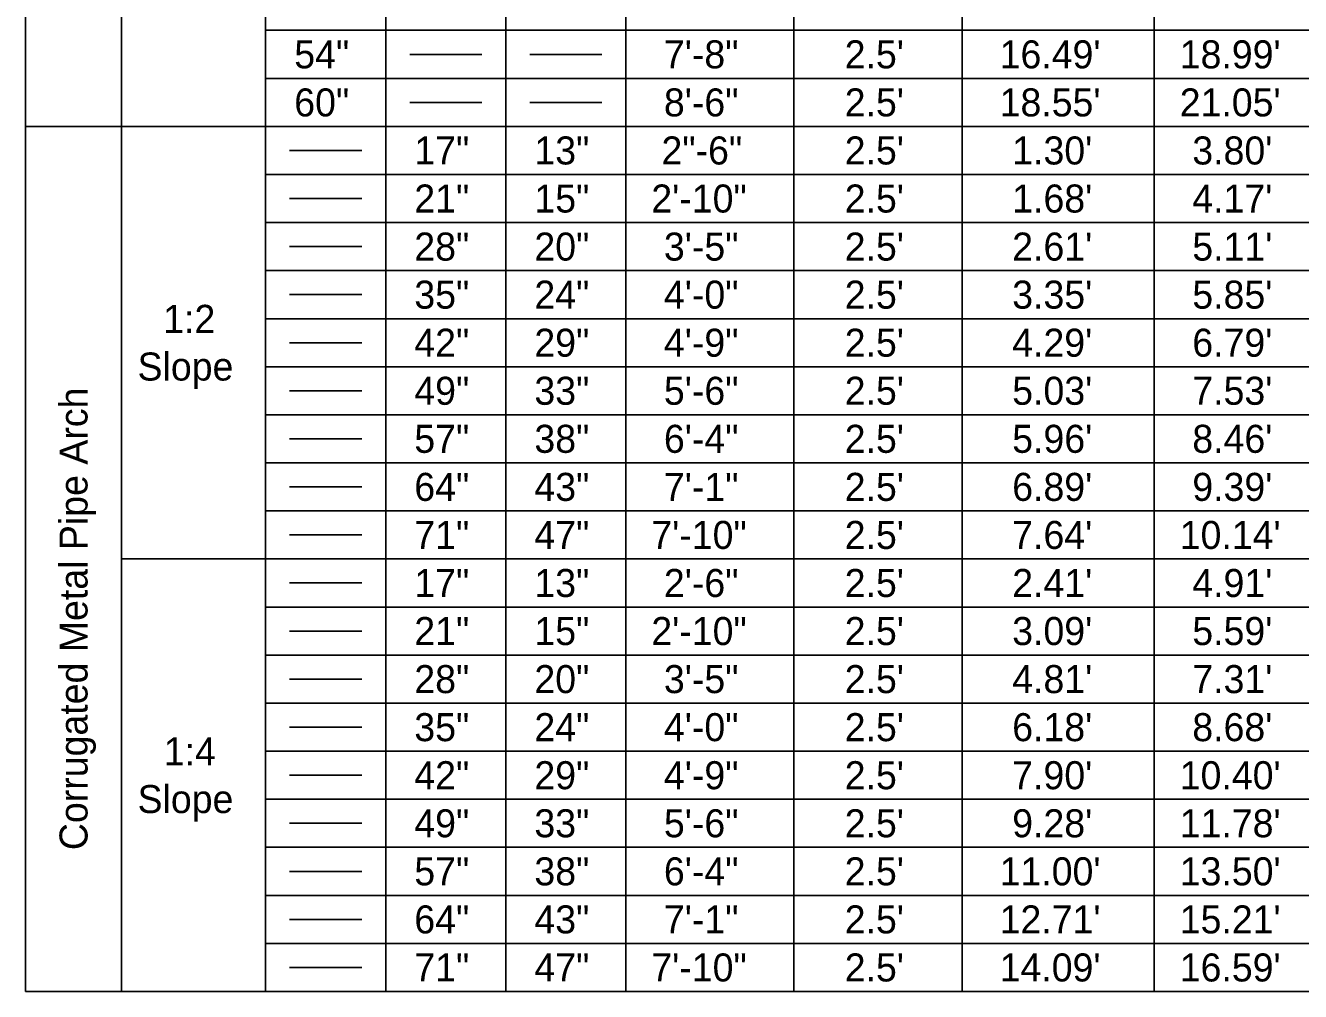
# Model space of a CAD drawing. Extents: x 1.7 to 14.4, y 0 to 7.8.
# Drawn here: x 1.7 to 4.886, y 2.49 to 4.902 of the extents above; entities that cross this region are included whole.
import ezdxf

# ---------------------------------------------------------------- set-up
doc = ezdxf.new("R2010")
doc.units = 0
doc.layers.add('Table', color=7, linetype='Continuous')

msp = doc.modelspace()

# ---------------------------------------------------------------- linework, layer by layer
at = {"layer": 'Table'}
for p, q in [((2.66, 4.83), (2.84, 4.83)), ((2.96, 4.83), (3.14, 4.83)), ((2.66, 4.71), (2.84, 4.71)), ((2.96, 4.71), (3.14, 4.71)), ((2.36, 4.59), (2.54, 4.59)), ((2.36, 4.47), (2.54, 4.47)), ((2.36, 4.35), (2.54, 4.35)), ((2.36, 4.23), (2.54, 4.23)), ((2.36, 4.11), (2.54, 4.11)), ((2.36, 3.99), (2.54, 3.99)), ((2.36, 3.87), (2.54, 3.87)), ((2.36, 3.75), (2.54, 3.75)), ((2.36, 3.63), (2.54, 3.63)), ((2.36, 3.51), (2.54, 3.51)), ((2.36, 3.39), (2.54, 3.39)), ((2.36, 3.27), (2.54, 3.27)), ((2.36, 3.15), (2.54, 3.15)), ((2.36, 3.03), (2.54, 3.03)), ((2.36, 2.91), (2.54, 2.91)), ((2.36, 2.79), (2.54, 2.79)), ((2.36, 2.67), (2.54, 2.67)), ((2.36, 2.55), (2.54, 2.55))]:
    msp.add_line(p, q, dxfattribs=at)
for points in [[(1.94, 7.7524), (1.94, 7.17), (1.94, 6.81), (1.94, 5.73), (1.94, 4.65), (1.94, 3.57), (1.94, 2.49)], [(1.7, 6.81), (1.7, 4.65), (1.7, 2.49)], [(2.3, 5.01), (2.3, 4.89), (2.3, 4.77), (2.3, 4.65), (2.3, 4.53), (2.3, 4.41), (2.3, 4.29), (2.3, 4.17), (2.3, 4.05), (2.3, 3.93), (2.3, 3.81), (2.3, 3.69), (2.3, 3.57), (2.3, 3.45), (2.3, 3.33), (2.3, 3.21), (2.3, 3.09), (2.3, 2.97), (2.3, 2.85), (2.3, 2.73), (2.3, 2.61), (2.3, 2.49)], [(2.6, 5.01), (2.6, 4.89), (2.6, 4.77), (2.6, 4.65), (2.6, 4.53), (2.6, 4.41), (2.6, 4.29), (2.6, 4.17), (2.6, 4.05), (2.6, 3.93), (2.6, 3.81), (2.6, 3.69), (2.6, 3.57), (2.6, 3.45), (2.6, 3.33), (2.6, 3.21), (2.6, 3.09), (2.6, 2.97), (2.6, 2.85), (2.6, 2.73), (2.6, 2.61), (2.6, 2.49)], [(2.9, 5.01), (2.9, 4.89), (2.9, 4.77), (2.9, 4.65), (2.9, 4.53), (2.9, 4.41), (2.9, 4.29), (2.9, 4.17), (2.9, 4.05), (2.9, 3.93), (2.9, 3.81), (2.9, 3.69), (2.9, 3.57), (2.9, 3.45), (2.9, 3.33), (2.9, 3.21), (2.9, 3.09), (2.9, 2.97), (2.9, 2.85), (2.9, 2.73), (2.9, 2.61), (2.9, 2.49)], [(3.2, 5.01), (3.2, 4.89), (3.2, 4.77), (3.2, 4.65), (3.2, 4.53), (3.2, 4.41), (3.2, 4.29), (3.2, 4.17), (3.2, 4.05), (3.2, 3.93), (3.2, 3.81), (3.2, 3.69), (3.2, 3.57), (3.2, 3.45), (3.2, 3.33), (3.2, 3.21), (3.2, 3.09), (3.2, 2.97), (3.2, 2.85), (3.2, 2.73), (3.2, 2.61), (3.2, 2.49)], [(3.62, 5.01), (3.62, 4.89), (3.62, 4.77), (3.62, 4.65), (3.62, 4.53), (3.62, 4.41), (3.62, 4.29), (3.62, 4.17), (3.62, 4.05), (3.62, 3.93), (3.62, 3.81), (3.62, 3.69), (3.62, 3.57), (3.62, 3.45), (3.62, 3.33), (3.62, 3.21), (3.62, 3.09), (3.62, 2.97), (3.62, 2.85), (3.62, 2.73), (3.62, 2.61), (3.62, 2.49)], [(4.04, 5.01), (4.04, 4.89), (4.04, 4.77), (4.04, 4.65), (4.04, 4.53), (4.04, 4.41), (4.04, 4.29), (4.04, 4.17), (4.04, 4.05), (4.04, 3.93), (4.04, 3.81), (4.04, 3.69), (4.04, 3.57), (4.04, 3.45), (4.04, 3.33), (4.04, 3.21), (4.04, 3.09), (4.04, 2.97), (4.04, 2.85), (4.04, 2.73), (4.04, 2.61), (4.04, 2.49)], [(4.52, 5.01), (4.52, 4.89), (4.52, 4.77), (4.52, 4.65), (4.52, 4.53), (4.52, 4.41), (4.52, 4.29), (4.52, 4.17), (4.52, 4.05), (4.52, 3.93), (4.52, 3.81), (4.52, 3.69), (4.52, 3.57), (4.52, 3.45), (4.52, 3.33), (4.52, 3.21), (4.52, 3.09), (4.52, 2.97), (4.52, 2.85), (4.52, 2.73), (4.52, 2.61), (4.52, 2.49)], [(2.3, 4.89), (2.6, 4.89), (2.9, 4.89), (3.2, 4.89), (3.62, 4.89), (4.04, 4.89), (4.52, 4.89), (4.94, 4.89), (5.3, 4.89), (5.66, 4.89), (6.02, 4.89), (6.38, 4.89), (6.8, 4.89), (7.22, 4.89), (7.64, 4.89), (8.06, 4.89), (8.42, 4.89)], [(2.3, 4.77), (2.6, 4.77), (2.9, 4.77), (3.2, 4.77), (3.62, 4.77), (4.04, 4.77), (4.52, 4.77), (4.94, 4.77), (5.3, 4.77), (5.66, 4.77), (6.02, 4.77), (6.38, 4.77), (6.8, 4.77), (7.22, 4.77), (7.64, 4.77), (8.06, 4.77), (8.42, 4.77)], [(1.7, 4.65), (1.94, 4.65), (2.3, 4.65), (2.6, 4.65), (2.9, 4.65), (3.2, 4.65), (3.62, 4.65), (4.04, 4.65), (4.52, 4.65), (4.94, 4.65), (5.3, 4.65), (5.66, 4.65), (6.02, 4.65), (6.38, 4.65), (6.8, 4.65), (7.22, 4.65), (7.64, 4.65), (8.06, 4.65), (8.42, 4.65)], [(2.3, 4.53), (2.6, 4.53), (2.9, 4.53), (3.2, 4.53), (3.62, 4.53), (4.04, 4.53), (4.52, 4.53), (4.94, 4.53), (5.3, 4.53), (5.66, 4.53), (6.02, 4.53), (6.38, 4.53), (6.8, 4.53), (7.22, 4.53), (7.64, 4.53), (8.06, 4.53), (8.42, 4.53)], [(2.3, 4.41), (2.6, 4.41), (2.9, 4.41), (3.2, 4.41), (3.62, 4.41), (4.04, 4.41), (4.52, 4.41), (4.94, 4.41), (5.3, 4.41), (5.66, 4.41), (6.02, 4.41), (6.38, 4.41), (6.8, 4.41), (7.22, 4.41), (7.64, 4.41), (8.06, 4.41), (8.42, 4.41)], [(2.3, 4.29), (2.6, 4.29), (2.9, 4.29), (3.2, 4.29), (3.62, 4.29), (4.04, 4.29), (4.52, 4.29), (4.94, 4.29), (5.3, 4.29), (5.66, 4.29), (6.02, 4.29), (6.38, 4.29), (6.8, 4.29), (7.22, 4.29), (7.64, 4.29), (8.06, 4.29), (8.42, 4.29)], [(2.3, 4.17), (2.6, 4.17), (2.9, 4.17), (3.2, 4.17), (3.62, 4.17), (4.04, 4.17), (4.52, 4.17), (4.94, 4.17), (5.3, 4.17), (5.66, 4.17), (6.02, 4.17), (6.38, 4.17), (6.8, 4.17), (7.22, 4.17), (7.64, 4.17), (8.06, 4.17), (8.42, 4.17)], [(2.3, 4.05), (2.6, 4.05), (2.9, 4.05), (3.2, 4.05), (3.62, 4.05), (4.04, 4.05), (4.52, 4.05), (4.94, 4.05), (5.3, 4.05), (5.66, 4.05), (6.02, 4.05), (6.38, 4.05), (6.8, 4.05), (7.22, 4.05), (7.64, 4.05), (8.06, 4.05), (8.42, 4.05)], [(2.3, 3.93), (2.6, 3.93), (2.9, 3.93), (3.2, 3.93), (3.62, 3.93), (4.04, 3.93), (4.52, 3.93), (4.94, 3.93), (5.3, 3.93), (5.66, 3.93), (6.02, 3.93), (6.38, 3.93), (6.8, 3.93), (7.22, 3.93), (7.64, 3.93), (8.06, 3.93), (8.42, 3.93)], [(2.3, 3.81), (2.6, 3.81), (2.9, 3.81), (3.2, 3.81), (3.62, 3.81), (4.04, 3.81), (4.52, 3.81), (4.94, 3.81), (5.3, 3.81), (5.66, 3.81), (6.02, 3.81), (6.38, 3.81), (6.8, 3.81), (7.22, 3.81), (7.64, 3.81), (8.06, 3.81), (8.42, 3.81)], [(2.3, 3.69), (2.6, 3.69), (2.9, 3.69), (3.2, 3.69), (3.62, 3.69), (4.04, 3.69), (4.52, 3.69), (4.94, 3.69), (5.3, 3.69), (5.66, 3.69), (6.02, 3.69), (6.38, 3.69), (6.8, 3.69), (7.22, 3.69), (7.64, 3.69), (8.06, 3.69), (8.42, 3.69)], [(1.94, 3.57), (2.3, 3.57), (2.6, 3.57), (2.9, 3.57), (3.2, 3.57), (3.62, 3.57), (4.04, 3.57), (4.52, 3.57), (4.94, 3.57), (5.3, 3.57), (5.66, 3.57), (6.02, 3.57), (6.38, 3.57), (6.8, 3.57), (7.22, 3.57), (7.64, 3.57), (8.06, 3.57), (8.42, 3.57)], [(2.3, 3.45), (2.6, 3.45), (2.9, 3.45), (3.2, 3.45), (3.62, 3.45), (4.04, 3.45), (4.52, 3.45), (4.94, 3.45), (5.3, 3.45), (5.66, 3.45), (6.02, 3.45), (6.38, 3.45), (6.8, 3.45), (7.22, 3.45), (7.64, 3.45), (8.06, 3.45), (8.42, 3.45)], [(2.3, 3.33), (2.6, 3.33), (2.9, 3.33), (3.2, 3.33), (3.62, 3.33), (4.04, 3.33), (4.52, 3.33), (4.94, 3.33), (5.3, 3.33), (5.66, 3.33), (6.02, 3.33), (6.38, 3.33), (6.8, 3.33), (7.22, 3.33), (7.64, 3.33), (8.06, 3.33), (8.42, 3.33)], [(2.3, 3.21), (2.6, 3.21), (2.9, 3.21), (3.2, 3.21), (3.62, 3.21), (4.04, 3.21), (4.52, 3.21), (4.94, 3.21), (5.3, 3.21), (5.66, 3.21), (6.02, 3.21), (6.38, 3.21), (6.8, 3.21), (7.22, 3.21), (7.64, 3.21), (8.06, 3.21), (8.42, 3.21)], [(2.3, 3.09), (2.6, 3.09), (2.9, 3.09), (3.2, 3.09), (3.62, 3.09), (4.04, 3.09), (4.52, 3.09), (4.94, 3.09), (5.3, 3.09), (5.66, 3.09), (6.02, 3.09), (6.38, 3.09), (6.8, 3.09), (7.22, 3.09), (7.64, 3.09), (8.06, 3.09), (8.42, 3.09)], [(2.3, 2.97), (2.6, 2.97), (2.9, 2.97), (3.2, 2.97), (3.62, 2.97), (4.04, 2.97), (4.52, 2.97), (4.94, 2.97), (5.3, 2.97), (5.66, 2.97), (6.02, 2.97), (6.38, 2.97), (6.8, 2.97), (7.22, 2.97), (7.64, 2.97), (8.06, 2.97), (8.42, 2.97)], [(2.3, 2.85), (2.6, 2.85), (2.9, 2.85), (3.2, 2.85), (3.62, 2.85), (4.04, 2.85), (4.52, 2.85), (4.94, 2.85), (5.3, 2.85), (5.66, 2.85), (6.02, 2.85), (6.38, 2.85), (6.8, 2.85), (7.22, 2.85), (7.64, 2.85), (8.06, 2.85), (8.42, 2.85)], [(2.3, 2.73), (2.6, 2.73), (2.9, 2.73), (3.2, 2.73), (3.62, 2.73), (4.04, 2.73), (4.52, 2.73), (4.94, 2.73), (5.3, 2.73), (5.66, 2.73), (6.02, 2.73), (6.38, 2.73), (6.8, 2.73), (7.22, 2.73), (7.64, 2.73), (8.06, 2.73), (8.42, 2.73)], [(2.3, 2.61), (2.6, 2.61), (2.9, 2.61), (3.2, 2.61), (3.62, 2.61), (4.04, 2.61), (4.52, 2.61), (4.94, 2.61), (5.3, 2.61), (5.66, 2.61), (6.02, 2.61), (6.38, 2.61), (6.8, 2.61), (7.22, 2.61), (7.64, 2.61), (8.06, 2.61), (8.42, 2.61)], [(1.7, 2.49), (1.94, 2.49), (2.3, 2.49), (2.6, 2.49), (2.9, 2.49), (3.2, 2.49), (3.62, 2.49), (4.04, 2.49), (4.52, 2.49), (4.94, 2.49), (5.3, 2.49), (5.66, 2.49), (6.02, 2.49), (6.38, 2.49), (6.8, 2.49), (7.22, 2.49), (7.64, 2.49), (8.06, 2.49), (8.42, 2.49)]]:
    msp.add_lwpolyline(points, dxfattribs=at)

# ---------------------------------------------------------------- texts
for s, rotation, p in [('54"', 0, (2.3715, 4.795)), ('7\'-8"', 0, (3.2951, 4.795)), ("2.5'", 0, (3.7469, 4.795)), ("16.49'", 0, (4.134, 4.795)), ("18.99'", 0, (4.584, 4.795)), ('60"', 0, (2.3715, 4.675)), ('8\'-6"', 0, (3.2951, 4.675)), ("2.5'", 0, (3.7469, 4.675)), ("18.55'", 0, (4.134, 4.675)), ("21.05'", 0, (4.584, 4.675)), ('17"', 0, (2.6715, 4.555)), ('13"', 0, (2.9715, 4.555)), ('2"-6"', 0, (3.289, 4.555)), ("2.5'", 0, (3.7469, 4.555)), ("1.30'", 0, (4.1654, 4.555)), ("3.80'", 0, (4.6154, 4.555)), ('21"', 0, (2.6715, 4.435)), ('15"', 0, (2.9715, 4.435)), ('2\'-10"', 0, (3.2637, 4.435)), ("2.5'", 0, (3.7469, 4.435)), ("1.68'", 0, (4.1654, 4.435)), ("4.17'", 0, (4.6154, 4.435)), ('28"', 0, (2.6715, 4.315)), ('20"', 0, (2.9715, 4.315)), ('3\'-5"', 0, (3.2951, 4.315)), ("2.5'", 0, (3.7469, 4.315)), ("2.61'", 0, (4.1654, 4.315)), ("5.11'", 0, (4.6154, 4.315)), ('35"', 0, (2.6715, 4.195)), ('24"', 0, (2.9715, 4.195)), ('4\'-0"', 0, (3.2951, 4.195)), ("2.5'", 0, (3.7469, 4.195)), ("3.35'", 0, (4.1654, 4.195)), ("5.85'", 0, (4.6154, 4.195)), ('42"', 0, (2.6715, 4.075)), ('29"', 0, (2.9715, 4.075)), ('4\'-9"', 0, (3.2951, 4.075)), ("2.5'", 0, (3.7469, 4.075)), ("4.29'", 0, (4.1654, 4.075)), ("6.79'", 0, (4.6154, 4.075)), ('49"', 0, (2.6715, 3.955)), ('33"', 0, (2.9715, 3.955)), ('5\'-6"', 0, (3.2951, 3.955)), ("2.5'", 0, (3.7469, 3.955)), ("5.03'", 0, (4.1654, 3.955)), ("7.53'", 0, (4.6154, 3.955)), ('Corrugated Metal Pipe Arch', 90, (1.855, 2.8429)), ('57"', 0, (2.6715, 3.835)), ('38"', 0, (2.9715, 3.835)), ('6\'-4"', 0, (3.2951, 3.835)), ("2.5'", 0, (3.7469, 3.835)), ("5.96'", 0, (4.1654, 3.835)), ("8.46'", 0, (4.6154, 3.835)), ('64"', 0, (2.6715, 3.715)), ('43"', 0, (2.9715, 3.715)), ('7\'-1"', 0, (3.2951, 3.715)), ("2.5'", 0, (3.7469, 3.715)), ("6.89'", 0, (4.1654, 3.715)), ("9.39'", 0, (4.6154, 3.715)), ('71"', 0, (2.6715, 3.595)), ('47"', 0, (2.9715, 3.595)), ('7\'-10"', 0, (3.2637, 3.595)), ("2.5'", 0, (3.7469, 3.595)), ("7.64'", 0, (4.1654, 3.595)), ("10.14'", 0, (4.584, 3.595)), ('17"', 0, (2.6715, 3.475)), ('13"', 0, (2.9715, 3.475)), ('2\'-6"', 0, (3.2951, 3.475)), ("2.5'", 0, (3.7469, 3.475)), ("2.41'", 0, (4.1654, 3.475)), ("4.91'", 0, (4.6154, 3.475)), ('21"', 0, (2.6715, 3.355)), ('15"', 0, (2.9715, 3.355)), ('2\'-10"', 0, (3.2637, 3.355)), ("2.5'", 0, (3.7469, 3.355)), ("3.09'", 0, (4.1654, 3.355)), ("5.59'", 0, (4.6154, 3.355)), ('28"', 0, (2.6715, 3.235)), ('20"', 0, (2.9715, 3.235)), ('3\'-5"', 0, (3.2951, 3.235)), ("2.5'", 0, (3.7469, 3.235)), ("4.81'", 0, (4.1654, 3.235)), ("7.31'", 0, (4.6154, 3.235)), ('35"', 0, (2.6715, 3.115)), ('24"', 0, (2.9715, 3.115)), ('4\'-0"', 0, (3.2951, 3.115)), ("2.5'", 0, (3.7469, 3.115)), ("6.18'", 0, (4.1654, 3.115)), ("8.68'", 0, (4.6154, 3.115)), ('42"', 0, (2.6715, 2.995)), ('29"', 0, (2.9715, 2.995)), ('4\'-9"', 0, (3.2951, 2.995)), ("2.5'", 0, (3.7469, 2.995)), ("7.90'", 0, (4.1654, 2.995)), ("10.40'", 0, (4.584, 2.995)), ('49"', 0, (2.6715, 2.875)), ('33"', 0, (2.9715, 2.875)), ('5\'-6"', 0, (3.2951, 2.875)), ("2.5'", 0, (3.7469, 2.875)), ("9.28'", 0, (4.1654, 2.875)), ("11.78'", 0, (4.584, 2.875)), ('57"', 0, (2.6715, 2.755)), ('38"', 0, (2.9715, 2.755)), ('6\'-4"', 0, (3.2951, 2.755)), ("2.5'", 0, (3.7469, 2.755)), ("11.00'", 0, (4.134, 2.755)), ("13.50'", 0, (4.584, 2.755)), ('64"', 0, (2.6715, 2.635)), ('43"', 0, (2.9715, 2.635)), ('7\'-1"', 0, (3.2951, 2.635)), ("2.5'", 0, (3.7469, 2.635)), ("12.71'", 0, (4.134, 2.635)), ("15.21'", 0, (4.584, 2.635)), ('71"', 0, (2.6715, 2.515)), ('47"', 0, (2.9715, 2.515)), ('7\'-10"', 0, (3.2637, 2.515)), ("2.5'", 0, (3.7469, 2.515)), ("14.09'", 0, (4.134, 2.515)), ("16.59'", 0, (4.584, 2.515))]:
    msp.add_text(s, height=0.07, rotation=rotation, dxfattribs=at).set_placement(p)
for s, p in [('1:2', (2.0441, 4.1345)), ('Slope', (1.98, 4.0155)), ('1:4', (2.0455, 3.0545)), ('Slope', (1.98, 2.9355))]:
    msp.add_text(s, height=0.07, dxfattribs=at).set_placement(p)

doc.saveas('drawing.dxf')
